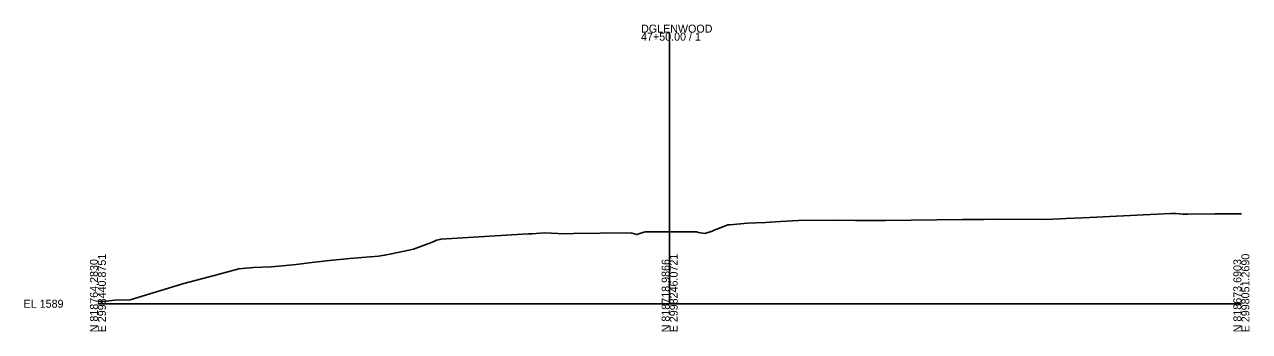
# Model space of a CAD drawing. Extents: x -26 to 2998358, y -10 to 818633.
# Drawn here: x -25.7 to 402.8, y -9.7 to 97.6 of the extents above; entities that cross this region are included whole.
import ezdxf

# ---------------------------------------------------------------- set-up
doc = ezdxf.new("R2010")
doc.units = 0
doc.layers.add('DESIGN - SHEET - Light Grid', color=7, linetype='Continuous')
doc.layers.add('SURVEY - GROUND - Top of Ground', color=7, linetype='Continuous')

msp = doc.modelspace()

# ---------------------------------------------------------------- linework, layer by layer
at = {"layer": 'DESIGN - SHEET - Light Grid'}
for p, q in [((200, 0), (200, 94.73)), ((0, 0), (200, 0)), ((200, 0), (400, 0))]:
    msp.add_line(p, q, dxfattribs=at)
at = {"layer": 'SURVEY - GROUND - Top of Ground'}
msp.add_lwpolyline([(0, 0.86), (1.28, 0.81), (1.67, 0.82), (5.92, 1.21), (11.27, 1.32), (30.08, 7.07), (41.08, 10), (49.29, 12.14), (54.36, 12.63), (60.57, 12.84), (64.45, 13.2), (69.4, 13.74), (74.82, 14.42), (80.99, 15.07), (88.13, 15.77), (92.36, 16.16), (98.09, 16.61), (100.27, 16.94), (102.7, 17.42), (110.38, 19.11), (117.26, 21.67), (118.46, 22.21), (119.58, 22.47), (119.94, 22.51), (148.49, 24.34), (150.58, 24.43), (151.94, 24.45), (156.09, 24.72), (163.32, 24.41), (166.39, 24.57), (184.97, 24.74), (186.78, 24.66), (188.52, 24.19), (190.92, 25.01), (191.47, 25.14), (200, 25.13), (205.5, 25.13), (209.35, 25.11), (210.07, 24.95), (212.32, 24.57), (214.86, 25.41), (215.54, 25.75), (219.49, 27.22), (220.4, 27.57), (221, 27.62), (227.18, 28.16), (230.19, 28.27), (233.5, 28.39), (238.78, 28.73), (245.06, 29.06), (258.27, 29.2), (264.96, 29.03), (275.48, 29.11), (302.43, 29.43), (309.88, 29.43), (315.04, 29.55), (331.93, 29.45), (338.68, 29.84), (344.53, 30.01), (370.51, 31.27), (375.35, 31.58), (377.17, 31.53), (379.53, 31.32), (381.33, 31.32), (390.76, 31.44), (400, 31.45)], dxfattribs=at)

# ---------------------------------------------------------------- texts
at = {"layer": 'DESIGN - SHEET - Light Grid'}
for s, p in [('47+50.00 / 1', (190, 91.93)), ('DGLENWOOD', (190, 94.73)), ('EL 1589', (-26, -1.4))]:
    msp.add_text(s, height=2.8, dxfattribs=at).set_placement(p)
for s, p in [('E 2998440.8751', (2.8, -10)), ('E 2998246.0721', (202.8, -10)), ('E 2998051.2690', (402.8, -10)), ('N 818764.2830', (0, -10)), ('N 818718.9866', (200, -10)), ('N 818673.6903', (400, -10))]:
    msp.add_text(s, height=2.8, rotation=90, dxfattribs=at).set_placement(p)

doc.saveas('drawing.dxf')
